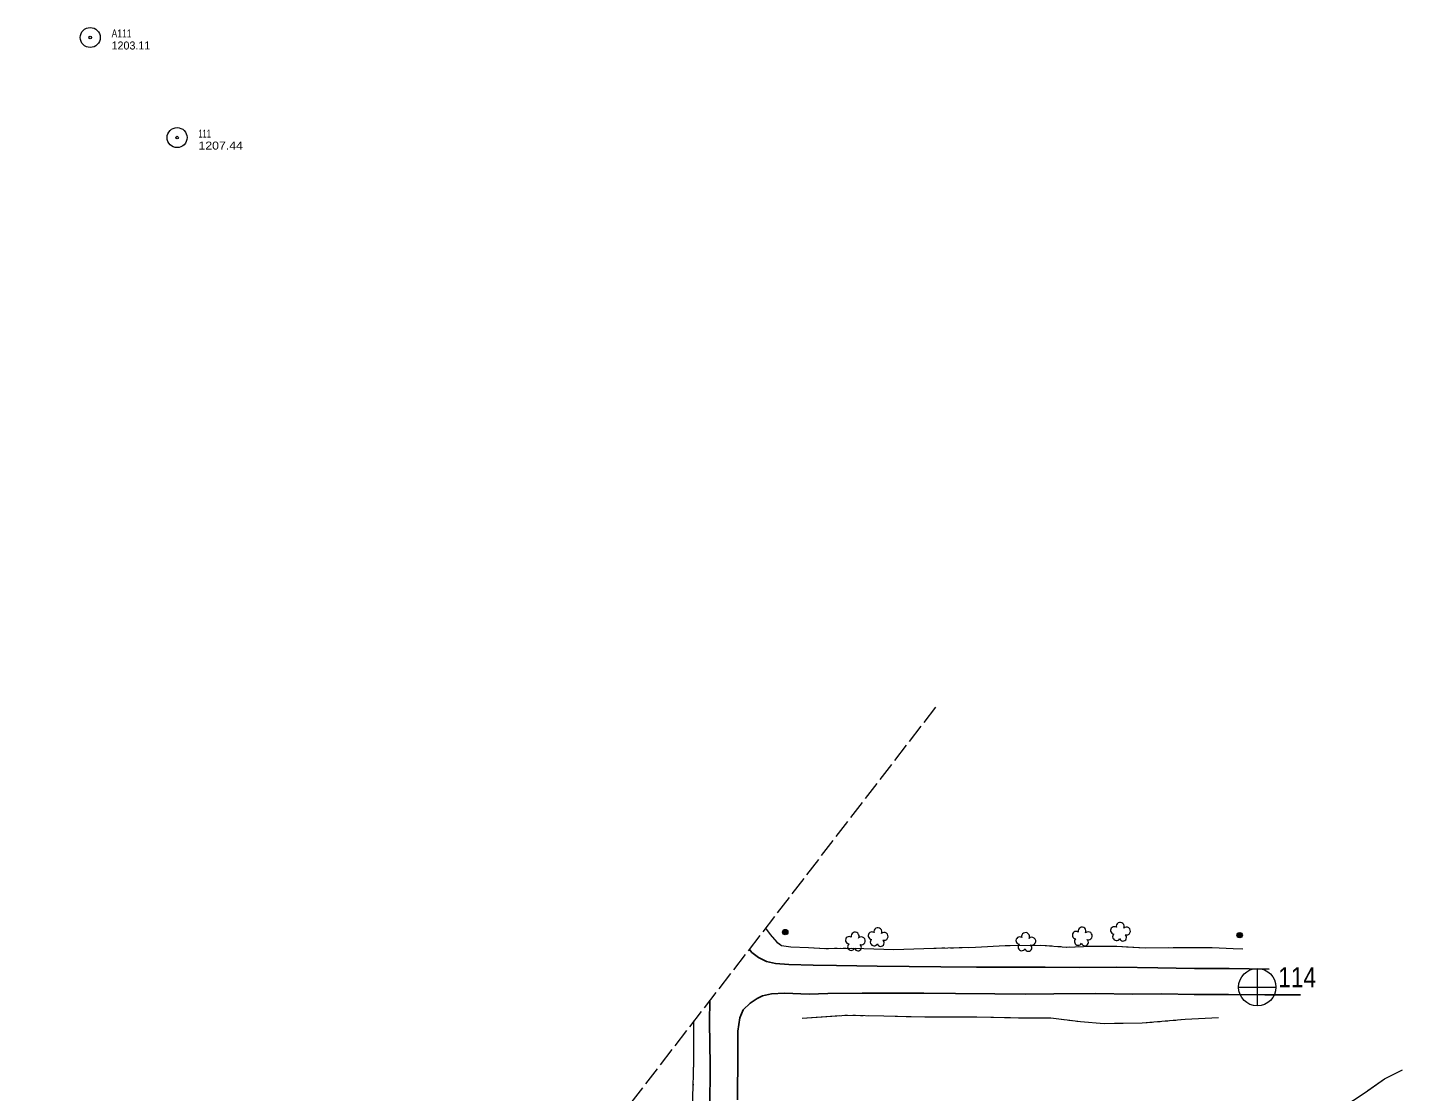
# Model space of a CAD drawing. Extents: x 299311 to 301657, y 49513 to 51866.
# Drawn here: x 299872 to 300903, y 51068 to 51866 of the extents above; entities that cross this region are included whole.
import ezdxf

# ---------------------------------------------------------------- set-up
doc = ezdxf.new("R2010")
doc.units = 0
doc.header["$LTSCALE"] = 2.4
doc.linetypes.add('LONG_DASHED', pattern=[7.5, 6, -1.5])
for name, color, linetype, lineweight in [('11', 7, 'Continuous', 25), ('14', 7, 'Continuous', 13), ('18', 7, 'Continuous', 13), ('19', 7, 'Continuous', 13), ('4', 7, 'Continuous', 13), ('6', 7, 'Continuous', 13)]:
    doc.layers.add(name, color=color, linetype=linetype, lineweight=lineweight)

msp = doc.modelspace()

# ---------------------------------------------------------------- linework, layer by layer
at = {"layer": '11'}
for points in [[(300442.725, 51163.565), (300432.919, 51164.314), (300426.131, 51165.955), (300420.037, 51168.846), (300415.18, 51172.592), (300413.167, 51175.22)], [(300802.901, 51160.158), (300772.765, 51160.594), (300746.771, 51160.576), (300719.426, 51161.106), (300688.665, 51161.764), (300660.859, 51161.433), (300634.9, 51161.733), (300613.332, 51161.765), (300583.586, 51161.687), (300556.774, 51161.828), (300533.087, 51162.154), (300508.939, 51162.282), (300478.581, 51162.872), (300461.129, 51163.043), (300442.725, 51163.565)], [(300383.606, 51055.158), (300383.946, 51088.145), (300383.438, 51120.333), (300383.678, 51136.919)], [(300404.294, 51062.123), (300404.559, 51096.335), (300404.65, 51113.73), (300406.057, 51123.606), (300408.676, 51129.69), (300413.745, 51134.673), (300418.965, 51138.127), (300422.976, 51140.142), (300429.827, 51141.636), (300439.644, 51142.068)], [(300826.248, 51141.024), (300799.545, 51140.889), (300772.498, 51141.118), (300746.726, 51141.186), (300722.369, 51141.62), (300700.59, 51141.377), (300672.473, 51141.858), (300641.472, 51141.604), (300619.84, 51141.458), (300597.288, 51141.606), (300567.711, 51141.833), (300543.91, 51142.087), (300522.187, 51142.086), (300497.715, 51142.23), (300472.097, 51141.997), (300458.067, 51141.516), (300439.644, 51142.068)]]:
    msp.add_lwpolyline(points, dxfattribs=at)
at = {"layer": '14'}
for centre, radius in [((300440.095, 51187.935), 2.018), ((300440.083, 51187.94), 1.518), ((300440.119, 51187.922), 1.008), ((300440.113, 51187.931), 0.502), ((300780.77, 51185.636), 2.018), ((300780.758, 51185.641), 1.518), ((300780.794, 51185.623), 1.008), ((300780.788, 51185.632), 0.502)]:
    msp.add_circle(centre, radius, dxfattribs=at)
at = {"layer": '18'}
for centre, radius, start, end in [((300492.492, 51184.872), 2.974, 332.7899, 194.02379), ((300505.078, 51185.253), 2.777, 55.76079, 263.53379), ((300509.526, 51188.269), 2.974, 332.7899, 194.02379), ((300514.218, 51184.769), 2.975, 250.44072, 133.41399), ((300620.259, 51184.584), 2.974, 332.7899, 194.02379), ((300658.123, 51185.655), 2.777, 55.76079, 263.53379), ((300662.571, 51188.671), 2.974, 332.7899, 194.02379), ((300667.263, 51185.171), 2.975, 250.44072, 133.41399), ((300686.739, 51189.239), 2.777, 55.76079, 263.53379), ((300691.187, 51192.255), 2.974, 332.7899, 194.02379), ((300695.879, 51188.755), 2.975, 250.44072, 133.41399), ((300488.044, 51181.856), 2.777, 55.76079, 263.53379), ((300489.61, 51177.043), 2.783, 132.43781, 333.44885), ((300494.62, 51176.481), 2.611, 195.14595, 53.07856), ((300497.184, 51181.372), 2.975, 250.44072, 133.41399), ((300506.644, 51180.44), 2.783, 132.43781, 333.44885), ((300511.654, 51179.878), 2.611, 195.14595, 53.07856), ((300615.811, 51181.568), 2.777, 55.76079, 263.53379), ((300617.377, 51176.755), 2.783, 132.43781, 333.44885), ((300622.387, 51176.193), 2.611, 195.14595, 53.07856), ((300624.951, 51181.084), 2.975, 250.44072, 133.41399), ((300659.689, 51180.842), 2.783, 132.43781, 333.44885), ((300664.699, 51180.28), 2.611, 195.14595, 53.07856), ((300688.305, 51184.426), 2.783, 132.43781, 333.44885), ((300693.315, 51183.864), 2.611, 195.14595, 53.07856)]:
    msp.add_arc(centre, radius, start, end, dxfattribs=at)
at = {"layer": '19'}
for p, q in [((300564.066, 51176.21), (300566.245, 51176.259)), ((300570.605, 51176.357), (300572.785, 51176.405)), ((300644.658, 51177.21), (300646.831, 51177.032)), ((300651.179, 51176.72), (300653.361, 51176.814)), ((300657.723, 51177), (300659.904, 51177.093)), ((300731.892, 51176.281), (300734.076, 51176.285)), ((300738.444, 51176.292), (300740.627, 51176.296)), ((300744.995, 51176.304), (300747.178, 51176.307)), ((300470.411, 51175.561), (300472.588, 51175.634)), ((300476.94, 51175.782), (300479.117, 51175.855)), ((300483.472, 51175.902), (300485.65, 51175.869)), ((300557.527, 51176.064), (300559.706, 51176.112)), ((300452.669, 51123.456), (300480.964, 51125.309)), ((300490.727, 51125.573), (300492.681, 51125.538)), ((300496.589, 51125.469), (300498.543, 51125.434)), ((300371.695, 51121.004), (300371.701, 51121.362)), ((300563.035, 51124.352), (300564.99, 51124.355)), ((300568.899, 51124.361), (300570.854, 51124.364)), ((300574.764, 51124.37), (300576.719, 51124.373)), ((300641.165, 51123.423), (300643.104, 51123.175)), ((300646.983, 51122.68), (300648.922, 51122.432)), ((300652.8, 51121.936), (300654.74, 51121.689)), ((300719.137, 51120.81), (300721.086, 51120.981)), ((300724.985, 51121.322), (300726.934, 51121.493)), ((300730.833, 51121.834), (300732.783, 51122.005)), ((300371.401, 51084.47), (300371.44, 51086.558)), ((300371.284, 51078.209), (300371.323, 51080.296))]:
    msp.add_line(p, q, dxfattribs=at)
for points in [[(300425.253, 51190.916), (300428.756, 51186.143), (300433.8, 51180.519), (300437.358, 51177.846), (300444.383, 51176.892), (300457.643, 51176.511), (300469.831, 51175.541), (300481.41, 51175.933), (300498.987, 51175.667), (300521.395, 51174.946), (300551.382, 51175.926), (300582.677, 51176.627), (300604.945, 51177.896), (300631.735, 51178.268), (300650.818, 51176.705), (300669.892, 51177.52), (300688.634, 51177.399), (300709.976, 51176.265), (300730.858, 51176.279), (300760.09, 51176.33), (300775.892, 51175.622), (300783.186, 51175.295)], [(300425.253, 51190.916), (300428.756, 51186.143), (300433.8, 51180.519), (300435.106, 51179.538)], [(300435.106, 51179.538), (300437.358, 51177.846), (300444.383, 51176.892), (300457.643, 51176.511), (300466.063, 51175.841)], [(300577.144, 51176.503), (300582.677, 51176.627), (300604.945, 51177.896), (300608.722, 51177.948)], [(300608.722, 51177.948), (300631.735, 51178.268), (300640.31, 51177.566)], [(300664.266, 51177.28), (300669.892, 51177.52), (300688.634, 51177.399), (300695.888, 51177.014)], [(300695.888, 51177.014), (300709.976, 51176.265), (300727.525, 51176.277)], [(300751.546, 51176.315), (300760.09, 51176.33), (300775.892, 51175.622), (300783.186, 51175.295)], [(300490.007, 51175.803), (300498.987, 51175.667), (300521.395, 51174.946), (300521.592, 51174.952)], [(300521.592, 51174.952), (300551.382, 51175.926), (300553.167, 51175.966)], [(300452.669, 51123.456), (300486.211, 51125.653), (300513.927, 51125.161), (300544.747, 51124.324), (300583.767, 51124.384), (300614.937, 51123.78), (300639.154, 51123.68), (300661.467, 51120.829), (300679.055, 51119.499), (300707.787, 51119.816), (300739.934, 51122.631), (300765.001, 51123.978)], [(300484.867, 51125.565), (300486.211, 51125.653), (300486.819, 51125.642)], [(300502.451, 51125.365), (300513.927, 51125.161), (300530.785, 51124.703)], [(300370.418, 51050.427), (300371.169, 51072.086), (300371.527, 51091.213), (300371.555, 51111.99), (300371.7, 51121.362)], [(300371.518, 51090.732), (300371.527, 51091.213), (300371.555, 51111.99), (300371.695, 51121.004)], [(300530.785, 51124.703), (300544.747, 51124.324), (300559.126, 51124.346)], [(300580.628, 51124.379), (300583.767, 51124.384), (300608.934, 51123.896)], [(300608.934, 51123.896), (300614.937, 51123.78), (300637.271, 51123.688)], [(300658.618, 51121.193), (300661.467, 51120.829), (300679.055, 51119.499), (300686.9, 51119.586)], [(300686.9, 51119.586), (300707.787, 51119.816), (300715.238, 51120.468)], [(300736.681, 51122.346), (300739.934, 51122.631), (300765.001, 51123.978)], [(300422.54, 50747.544), (300436.079, 50752.836), (300452.414, 50764.604), (300472.696, 50778.751), (300494.703, 50795.792), (300515.121, 50810.874), (300538.475, 50826.262), (300559.48, 50839.875), (300584.059, 50859.95), (300601.764, 50874.634), (300624.497, 50891.449), (300651.335, 50910.214), (300677.391, 50928.542), (300702.057, 50945.115), (300722.65, 50960.575), (300744.495, 50975.604), (300772.596, 50996.84), (300799.433, 51020.225), (300824.225, 51035.504), (300847.908, 51050.037), (300874.771, 51067.676), (300889.433, 51077.924), (300902.816, 51084.623)], [(300876.74, 51069.052), (300889.433, 51077.924), (300902.816, 51084.623)], [(300371.164, 51071.947), (300371.169, 51072.086), (300371.205, 51074.034)]]:
    msp.add_lwpolyline(points, dxfattribs=at)
at = {"layer": '4', "linetype": 'LONG_DASHED'}
msp.add_line((300552.76, 51356.525), (299872.076, 50472.442), dxfattribs=at)
at = {"layer": '4'}
for p, q in [((300793.889, 51160.689), (300793.824, 51132.835)), ((300779.98, 51146.659), (300807.885, 51146.646))]:
    msp.add_line(p, q, dxfattribs=at)
msp.add_circle((300793.941, 51146.667), 14, dxfattribs=at)
at = {"layer": '6'}
for centre, radius in [((299919.11, 51858.79), 7.5), ((299919.11, 51858.79), 0.96), ((299984.214, 51783.724), 7.5), ((299984.214, 51783.724), 0.96)]:
    msp.add_circle(centre, radius, dxfattribs=at)

# ---------------------------------------------------------------- texts
at = {"layer": '4', "width": 0.85}
msp.add_text('114', height=15, dxfattribs=at).set_placement((300809.593, 51146.597))
at = {"layer": '6'}
for s, width, p in [('A111', 0.8, (299935.11, 51858.79)), ('111', 0.7, (300000.214, 51783.724)), ('1207.44', 1.15, (300000.214, 51774.724))]:
    msp.add_text(s, height=6, dxfattribs=dict(at, width=width)).set_placement(p)
msp.add_text('1203.11', height=6, dxfattribs=at).set_placement((299935.11, 51849.79))

doc.saveas('drawing.dxf')
